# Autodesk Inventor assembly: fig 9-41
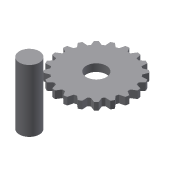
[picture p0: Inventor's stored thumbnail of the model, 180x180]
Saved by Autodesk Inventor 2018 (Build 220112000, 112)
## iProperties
Created: 2013-07
Part Number: fig 9-41
Document SubType Name: Assembly
Designer: CADCIM
Author: CADCIM
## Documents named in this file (3)
- E:\_Deepak\Inventor\Autodesk Inventor_2017_Project\Resources\Inventor_2018_Part\c09_Inv_2018\c09_inv_2018_prt\fig 9-41.iam
- E:\_Deepak\Inventor\Autodesk Inventor_2017_Project\Resources\Inventor_2018_Part\c09_Inv_2018\c09_inv_2018_prt\13.ipt
- E:\_Deepak\Inventor\Autodesk Inventor_2017_Project\Resources\Inventor_2018_Part\c09_Inv_2018\c09_inv_2018_prt\14.ipt
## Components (2 placed, 2 different names)
1. 13:1
2. 14:1
